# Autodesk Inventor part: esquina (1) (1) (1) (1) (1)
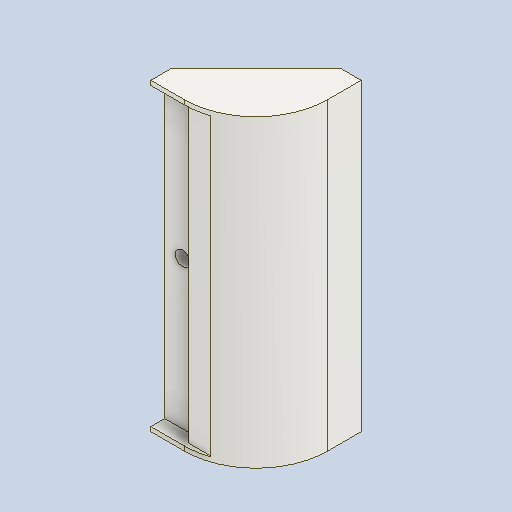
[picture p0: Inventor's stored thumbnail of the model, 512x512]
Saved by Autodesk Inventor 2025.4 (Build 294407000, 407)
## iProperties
Created: 2026-06
Part Number: esquina (1) (1) (1) (1) (1)
Material: Generic
Document SubType Name: Modeling
Designer: AdminForWorker
Density: 1 g/cm^3
Appearance: Default
Title: esquina (1) (1) (1) (1) (1)
Author: AdminForWorker
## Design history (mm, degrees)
feature "esquina (1) (1) (1) (1) (1)"
body "Solid1"
